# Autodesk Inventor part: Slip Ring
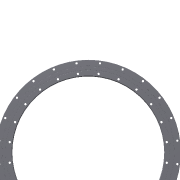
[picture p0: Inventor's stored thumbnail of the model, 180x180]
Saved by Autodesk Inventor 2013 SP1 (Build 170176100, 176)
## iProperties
Created: 2009-07
Part Number: Slip Ring
Document SubType Name: Modeling
Designer: ssc
Density: 7.86 g/cm^3
Material: Steel, Mild
Mass: 94630.1 g
Surface Area: 10759.4 cm^2
Volume: 12039.4 cm^3
Author: ssc
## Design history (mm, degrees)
sketch "Sketch1"
  geometry: C1 r 596.9 at (0, 0)
  constraints: 1 centre point, 1 other
  dimensions: "d0" = 1193.8 diameter of C1
extrude "Extrusion1" new body sketch "Sketch1" distance "d1" = 36.83; taper "d2" = 0 deg
hole "Hole1" diameter "d5" = 979.17; stored, may be unused: countersink angle "d9" = 82 deg, drill point angle "d11" = 118 deg; dims "d3" = 25.4, "d4" = 25.4, "d6" = 12.7, "d7" = 9.525, "d8" = 6.35, "d10" = 19.05
sketch "Sketch3"
  geometry: C1 r 489.585 at (0, 0) reference; 1 further point
  dimensions: "d93" = 510.54 distance of C1.centre point (66.639, 506.172)
hole "Hole2" sketch "Sketch3" diameter "d13" = 15.4686; stored, may be unused: countersink angle "d17" = 82 deg, drill point angle "d19" = 118 deg; dims "d14" = 12.7, "d15" = 9.525, "d16" = 6.35, "d18" = 19.05
workplane "Work Plane2"
workplane "Work Plane1"
sketch "Sketch8"
  geometry: L1 (551.993, 36.83)-(548.88, 29.838); L2 (548.88, 29.838)-(558.8, 29.838); L3 (558.8, 29.838)-(558.8, 36.83); L4 (533.4, 36.83)-(533.4, 29.838); L5 (533.4, 29.838)-(523.48, 29.838); L6 (523.48, 29.838)-(526.593, 36.83); L7 (0, 45.066)-(0, 6.227); L8 (526.593, 36.83)-(533.4, 36.83); L9 (551.993, 36.83)-(558.8, 36.83); L10 (0, -9.013)-(0, 54.079) reference; 1 further point
  constraints: 18 end point, 2 collinear, 2 equal length, 2 perpendicular
  dimensions: "d53" = 6.8072 distance of L6.end L4.start; "d57" = 6.8072 distance of L3.end L1.start; "d90" = 1066.8 diameter of L4 L7; "d91" = 1117.6 diameter of L3 L7
revolve "Revolution1" sketch "Sketch8" stored, may be unused: angle "d59" = 90 deg
fillet "Fillet1" dims "d60" = 0.508
fillet "Fillet2" dims "d61" = 0.381
chamfer "Chamfer2" distance "d63" = 1.524; stored, may be unused: second distance "d64" = 3.175, angle "d65" = 45 deg
sketch "Sketch10"
  geometry: C1 r 489.585 at (0, 0) reference; C2 r 526.006 at (0, 0) reference; C3 r 496.57 at (0, 0)
  constraints: 1 centre point, 1 coincident
  dimensions: "d66" = 993.14 diameter of C3
extrude "Extrusion5" cut sketch "Sketch10" distance "d67" = 2.54; taper "d68" = 0 deg
chamfer "Chamfer3" distance "d69" = 5.08; stored, may be unused: second distance "d70" = 3.175, angle "d71" = 45 deg
sketch "Sketch12"
  geometry: C1 r 496.57 at (0, 0) reference; 2 further points
  dimensions: "d95" = 579.12 distance of C1.centre point (75.59, 574.166)
hole "Hole5" sketch "Sketch12" at (75.59, 574.166) diameter "d96" = 15.4686; stored, may be unused: countersink angle "d100" = 82 deg, drill point angle "d102" = 118 deg; dims "d97" = 19.05, "d98" = 9.525, "d99" = 6.35, "d101" = 25.4
body "Solid1"
pattern_circular "Circular Pattern1" dims angle "d21" = 360 deg
pattern_circular "Circular Pattern4" dims angle "d105" = 360 deg
